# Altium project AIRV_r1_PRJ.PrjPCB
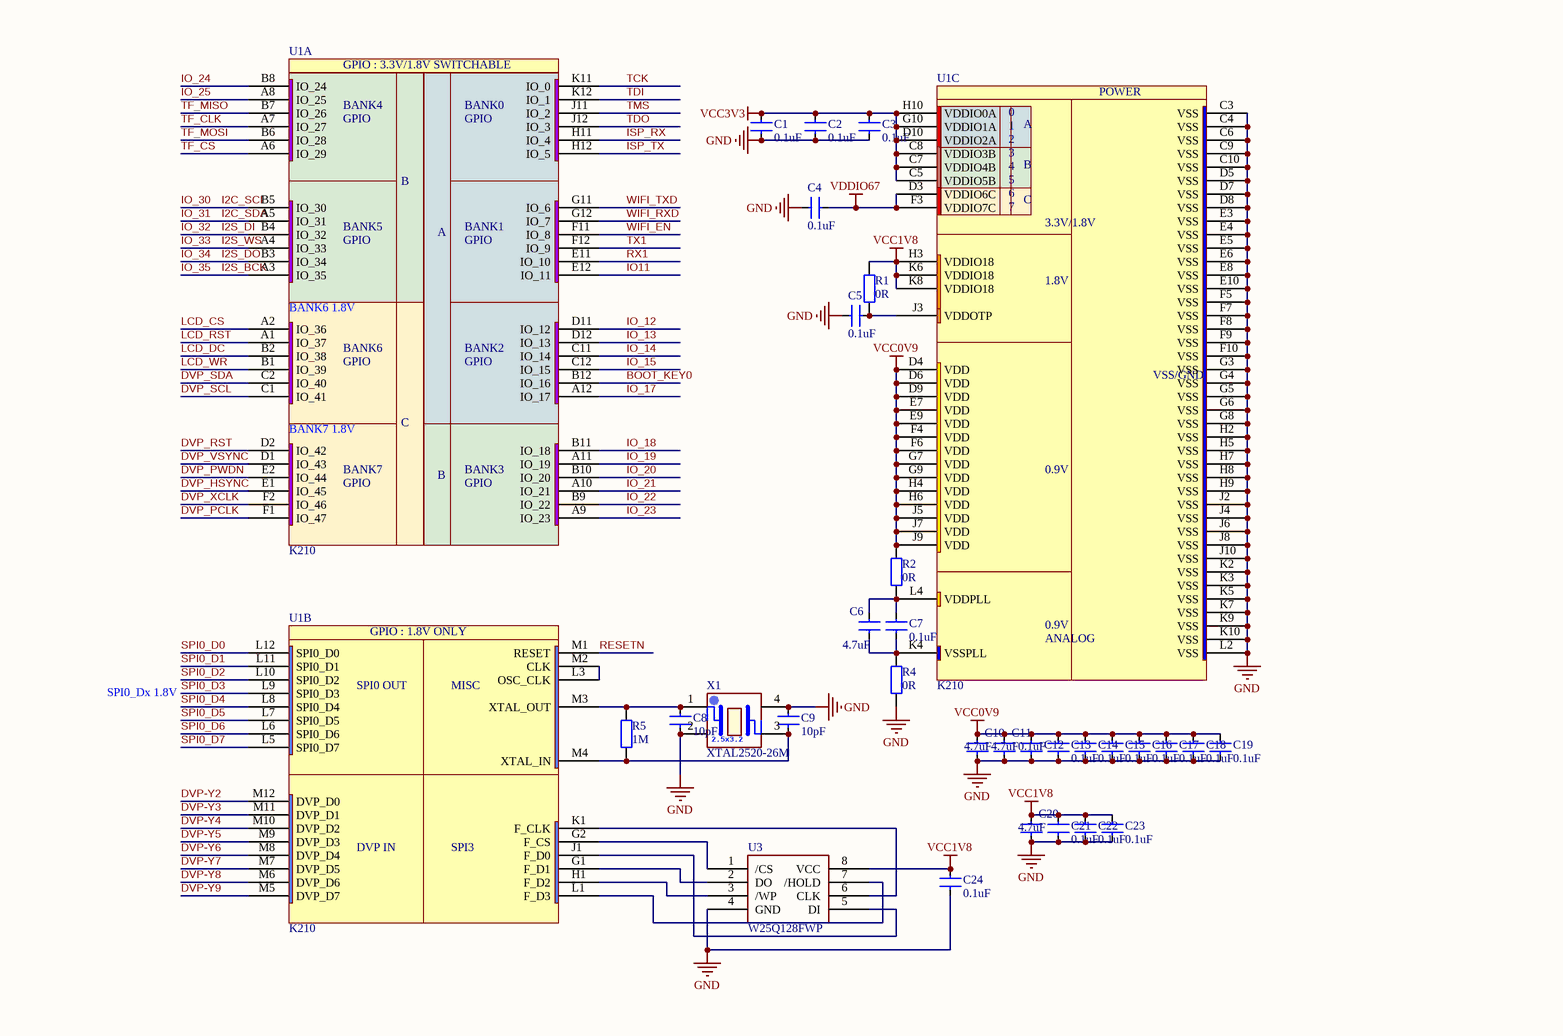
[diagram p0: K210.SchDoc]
2 sheets, 130 parts. Net scope: global (net labels, ports and power ports of the same name join across sheets).
Board file: AIRV_r1_nologo.PcbDoc
Sheets:
  K210.SchDoc
  Periph.SchDoc

## Sheet K210.SchDoc: RF
size A4; Date: 20150330; DrawnBy: mango; DocumentNumber: 1; SheetNumber: 1; SheetTotal: 7

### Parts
C1  0.1uF  [C0402]
C2  0.1uF  [C0402]
C3  0.1uF  [C0402]
C4  0.1uF  [C0402]
C5  0.1uF  [C0402]
C6  4.7uF  [C0402]
C7  0.1uF  [C0402]
C8  10pF  [C0402]
C9  10pF  [C0402]
C10  4.7uF  [C0402]
C11  4.7uF  [C0402]
C12  0.1uF  [C0402]
C13  0.1uF  [C0402]
C14  0.1uF  [C0402]
C15  0.1uF  [C0402]
C16  0.1uF  [C0402]
C17  0.1uF  [C0402]
C18  0.1uF  [C0402]
C19  0.1uF  [C0402]
C20  4.7uF  [C0402]
C21  0.1uF  [C0402]
C22  0.1uF  [C0402]
C23  0.1uF  [C0402]
C24  0.1uF  [C0402]
R1  0R  [R0402]
R2  0R  [R0402]
R4  0R  [R0402]
R5  1M  [R0402]
U1  K210  [BGA144C65P12X12_800X800X95]  (parts A,B,C of 3)
U3  W25Q128FWP  [WSON6X5]
X1  XTAL2520-26M  [XTAL2520]

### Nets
GND: C1.2 C2.2 C3.2 C4.2 C5.1 C8.1 C9.2 C10.1 C11.1 C12.1 C13.1 C14.1 C15.1 C16.1 C17.1 C18.1 C19.1 C20.1 C21.1 C22.1 C23.1 C24.1 R4.1 U1.C3(VSS) U1.C4(VSS) U1.C6(VSS) U1.C9(VSS) U1.C10(VSS) U1.D5(VSS) U1.D7(VSS) U1.D8(VSS) U1.E3(VSS) U1.E4(VSS) U1.E5(VSS) U1.E6(VSS) U1.E8(VSS) U1.E10(VSS) U1.F5(VSS) U1.F7(VSS) U1.F8(VSS) U1.F9(VSS) U1.F10(VSS) U1.G3(VSS) U1.G4(VSS) U1.G5(VSS) U1.G6(VSS) U1.G8(VSS) U1.H2(VSS) U1.H5(VSS) U1.H7(VSS) U1.H8(VSS) U1.H9(VSS) U1.J2(VSS) U1.J4(VSS) U1.J6(VSS) U1.J8(VSS) U1.J10(VSS) U1.K2(VSS) U1.K3(VSS) U1.K5(VSS) U1.K7(VSS) U1.K9(VSS) U1.K10(VSS) U1.L2(VSS) U3.4(GND) X1.2(NC1) X1.4(NC2)
VCC0V9: C10.2 C11.2 C12.2 C13.2 C14.2 C15.2 C16.2 C17.2 C18.2 C19.2 R2.2 U1.D4(VDD) U1.D6(VDD) U1.D9(VDD) U1.E7(VDD) U1.E9(VDD) U1.F4(VDD) U1.F6(VDD) U1.G7(VDD) U1.G9(VDD) U1.H4(VDD) U1.H6(VDD) U1.J5(VDD) U1.J7(VDD) U1.J9(VDD)
VCC1V8: C20.2 C21.2 C22.2 C23.2 C24.2 R1.1 U1.H3(VDDIO18) U1.K6(VDDIO18) U1.K8(VDDIO18) U3.8(VCC)
VCC3V3: C1.1 C2.1 C3.1 U1.C5(VDDIO5B) U1.C7(VDDIO4B) U1.C8(VDDIO3B) U1.D10(VDDIO2A) U1.G10(VDDIO1A) U1.H10(VDDIO0A)
VDDIO67: C4.1 U1.D3(VDDIO6C) U1.F3(VDDIO7C)
BOOT_KEY0: U1.B12(IO_16)
DVP-Y2: U1.M12(DVP_D0)
DVP-Y3: U1.M11(DVP_D1)
DVP-Y4: U1.M10(DVP_D2)
DVP-Y5: U1.M9(DVP_D3)
DVP-Y6: U1.M8(DVP_D4)
DVP-Y7: U1.M7(DVP_D5)
DVP-Y8: U1.M6(DVP_D6)
DVP-Y9: U1.M5(DVP_D7)
DVP_HSYNC: U1.E1(IO_45)
DVP_PCLK: U1.F1(IO_47)
DVP_PWDN: U1.E2(IO_44)
DVP_RST: U1.D2(IO_42)
DVP_SCL: U1.C1(IO_41)
DVP_SDA: U1.C2(IO_40)
DVP_VSYNC: U1.D1(IO_43)
DVP_XCLK: U1.F2(IO_46)
I2C_SCL: U1.B5(IO_30)  [also labelled IO_30]
I2C_SDA: U1.A5(IO_31)  [also labelled IO_31]
I2S_BCK: U1.A3(IO_35)  [also labelled IO_35]
I2S_DI: U1.B4(IO_32)  [also labelled IO_32]
I2S_DO: U1.B3(IO_34)  [also labelled IO_34]
I2S_WS: U1.A4(IO_33)  [also labelled IO_33]
IO11: U1.E12(IO_11)
IO_12: U1.D11(IO_12)
IO_13: U1.D12(IO_13)
IO_14: U1.C11(IO_14)
IO_15: U1.C12(IO_15)
IO_17: U1.A12(IO_17)
IO_18: U1.B11(IO_18)
IO_19: U1.A11(IO_19)
IO_20: U1.B10(IO_20)
IO_21: U1.A10(IO_21)
IO_22: U1.B9(IO_22)
IO_23: U1.A9(IO_23)
IO_24: U1.B8(IO_24)
IO_25: U1.A8(IO_25)
ISP_RX: U1.H11(IO_4)
ISP_TX: U1.H12(IO_5)
LCD_CS: U1.A2(IO_36)
LCD_DC: U1.B2(IO_38)
LCD_RST: U1.A1(IO_37)
LCD_WR: U1.B1(IO_39)
RESETN: U1.M1(RESET)
RX1: U1.E11(IO_10)
SPI0_D0: U1.L12(SPI0_D0)
SPI0_D1: U1.L11(SPI0_D1)
SPI0_D2: U1.L10(SPI0_D2)
SPI0_D3: U1.L9(SPI0_D3)
SPI0_D4: U1.L8(SPI0_D4)
SPI0_D5: U1.L7(SPI0_D5)
SPI0_D6: U1.L6(SPI0_D6)
SPI0_D7: U1.L5(SPI0_D7)
TCK: U1.K11(IO_0)
TDI: U1.K12(IO_1)
TDO: U1.J12(IO_3)
TF_CLK: U1.A7(IO_27)
TF_CS: U1.A6(IO_29)
TF_MISO: U1.B7(IO_26)
TF_MOSI: U1.B6(IO_28)
TMS: U1.J11(IO_2)
TX1: U1.F12(IO_9)
WIFI_EN: U1.F11(IO_8)
WIFI_RXD: U1.G12(IO_7)
WIFI_TXD: U1.G11(IO_6)
NetC5_2: C5.2 R1.2 U1.J3(VDDOTP)
NetC6_1: C6.1 C7.1 R4.2 U1.K4(VSSPLL)
NetC6_2: C6.2 C7.2 R2.1 U1.L4(VDDPLL)
NetC8_2: C8.2 R5.1 U1.M3(XTAL_OUT) X1.1(X1)
NetC9_1: C9.1 R5.2 U1.M4(XTAL_IN) X1.3(X2)
NetU1_G1: U1.G1(F_D1) U3.2(DO)
NetU1_G2: U1.G2(F_CS) U3.1(/CS)
NetU1_H1: U1.H1(F_D2) U3.3(/WP)
NetU1_J1: U1.J1(F_D0) U3.5(DI)
NetU1_K1: U1.K1(F_CLK) U3.6(CLK)
NetU1_L1: U1.L1(F_D3) U3.7(/HOLD)
NetU1_L3: U1.L3(OSC_CLK) U1.M2(CLK)

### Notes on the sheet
- (near U1) BANK6 1.8V
- (near U1) BANK7 1.8V
- SPI0_Dx 1.8V

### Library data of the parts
C1-C24 = CAP: 普通小电容
R1 R2 R4 R5 = RES: 普通电阻
U1 = K210: Canaan Kendryte K210 AI SoC; VENDOR: CANAAN INC.
U3 = SPIFLASH_SOP8W
X1 = XTAL3225

## Sheet Periph.SchDoc
size A3; DocumentNumber: 3; SheetNumber: 3; SheetTotal: 7
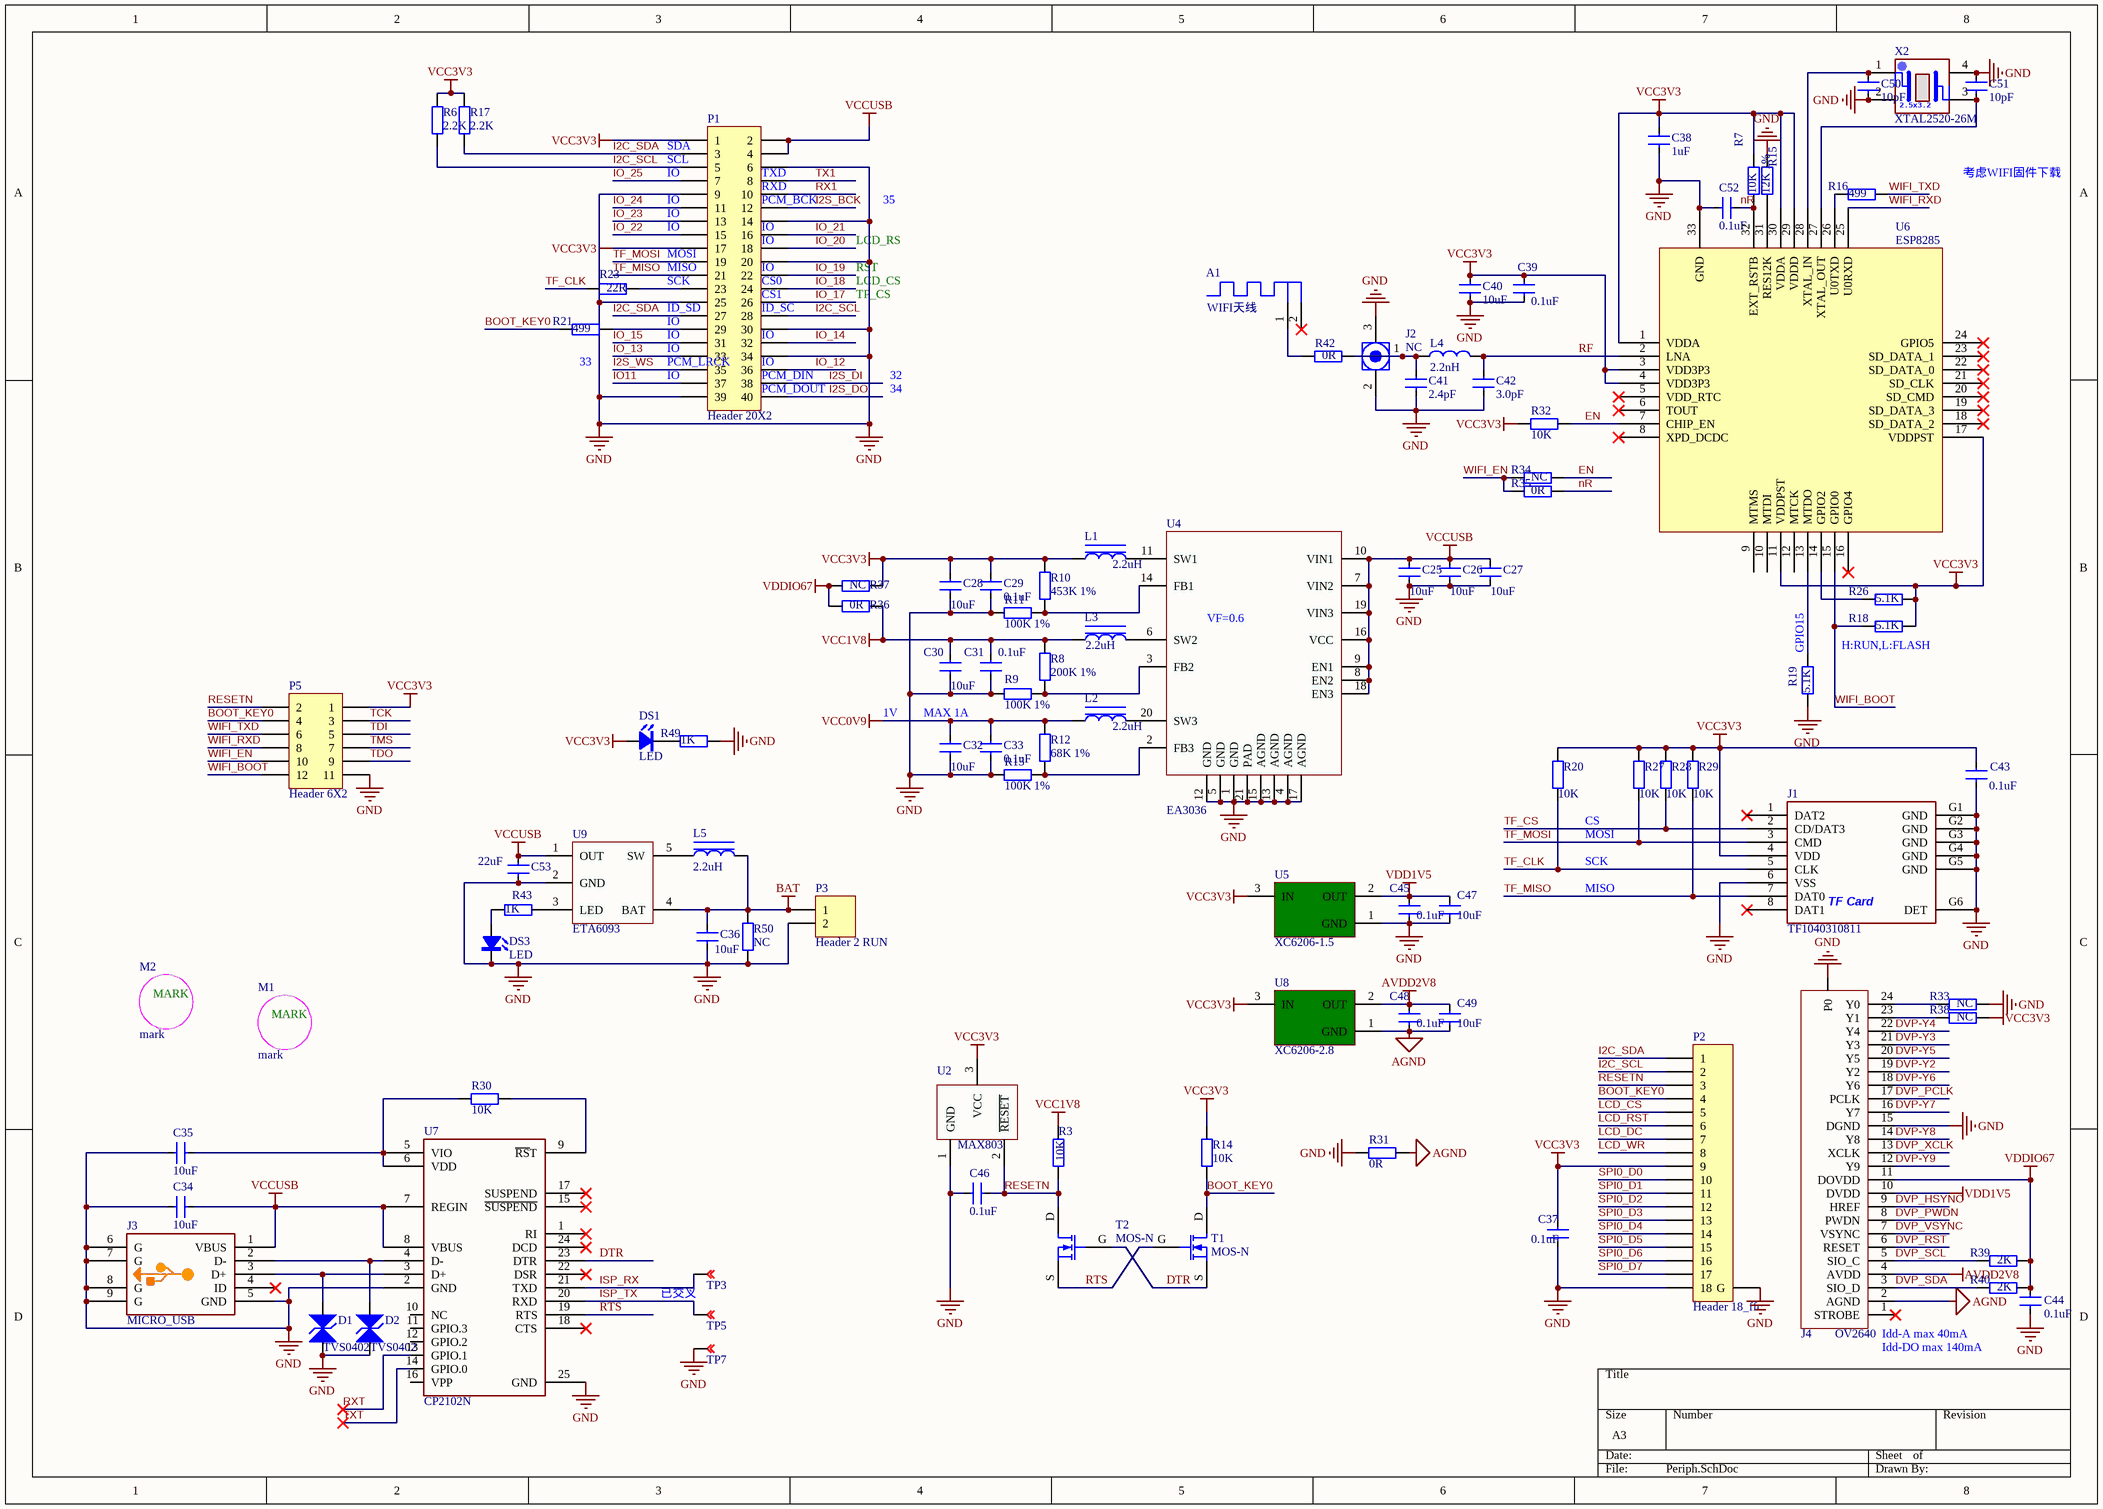
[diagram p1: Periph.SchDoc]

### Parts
A1  WIFI天线  [AN3216]
C25  10uF  [C0402]
C26  10uF  [C0402]
C27  10uF  [C0402]
C28  10uF  [C0402]
C29  0.1uF  [C0402]
C30  10uF  [C0402]
C31  0.1uF  [C0402]
C32  10uF  [C0402]
C33  0.1uF  [C0402]
C34  10uF  [C0402]
C35  10uF  [C0402]
C36  10uF  [C0402]
C37  0.1uF  [C0402]
C38  1uF  [C0402]
C39  0.1uF  [C0402]
C40  10uF  [C0402]
C41  2.4pF  [C0402]
C42  3.0pF  [C0402]
C43  0.1uF  [C0402]
C44  0.1uF  [C0402]
C45  0.1uF  [C0402]
C46  0.1uF  [C0402]
C47  10uF  [C0402]
C48  0.1uF  [C0402]
C49  10uF  [C0402]
C50  10pF  [C0402]
C51  10pF  [C0402]
C52  0.1uF  [C0402]
C53  22uF  [C0603]
D1  TVS0402  [0402TVS]
D2  TVS0402  [0402TVS]
DS1  LED  [LED0603]
DS3  LED  [LED0603]
J1  TF1040310811  [TFCARD-1040310811]
J2  NC  [I-PEX SOCKET]
J3  MICRO_USB  [MICROUSB]
J4  OV2640  [FFC/SM0.5-2H24-OV5640]
L1  2.2uH  [VLS2016]
L2  2.2uH  [VLS2016]
L3  2.2uH  [VLS2016]
L4  2.2nH  [L0402]
L5  2.2uH  [VLS2016]
M1  mark  [ZY_UR-3X2]
M2  mark  [MARKER-C]
P1  Header 20X2  [HDR2X20]
P2  Header 18_ffc  [FFC/SM0.5-1H18]
P3  Header 2 RUN  [HDR1X2]
P5  Header 6X2  [HDR1.27-6x2]
R3  10K  [R0402]
R6  2.2K  [R0402]
R7  10K  [R0402]
R8  200K 1%  [R0402]
R9  100K 1%  [R0402]
R10  453K 1%  [R0402]
R11  100K 1%  [R0402]
R12  68K 1%  [R0402]
R13  100K 1%  [R0402]
R14  10K  [R0402]
R15  12K 1%  [R0402]
R16  499  [R0402]
R17  2.2K  [R0402]
R18  5.1K  [R0402]
R19  5.1K  [R0402]
R20  10K  [R0402]
R21  499  [R0402]
R23  22R  [R0402]
R26  5.1K  [R0402]
R27  10K  [R0402]
R28  10K  [R0402]
R29  10K  [R0402]
R30  10K  [R0402]
R31  0R  [R0402]
R32  10K  [R0402]
R33  NC  [R0402]
R34  NC  [R0402]
R35  0R  [R0402]
R36  0R  [R0402]
R37  NC  [R0402]
R38  NC  [R0402]
R39  2K  [R0402]
R40  2K  [R0402]
R42  0R  [R0402]
R43  1K  [R0402]
R49  1K  [R0402]
R50  NC  [R0402]
T1  MOS-N  [SOT23]
T2  MOS-N  [SOT23]
TP3  TEST POINT  [TEST-POINT]  (value not drawn)
TP5  TEST POINT  [TEST-POINT]  (value not drawn)
TP7  TEST POINT  [TEST-POINT]  (value not drawn)
U2  MAX803  [SOT23]
U4  EA3036  [QFN40P300X300X80_HS-21N]
U5  XC6206-1.5  [SOT23]
U6  ESP8285  [QFN32]
U7  CP2102N  [QFN24]
U8  XC6206-2.8  [SOT23]
U9  ETA6093  [SOT23-5]
X2  XTAL2520-26M  [XTAL2520]

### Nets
AGND: C48.1 C49.2 J4.2(AGND) R31.2 U8.1(GND)
AVDD2V8: C48.2 C49.1 J4.4(AVDD) U8.2(OUT)
BAT: C36.1 L5.1 P3.1 R50.1 U9.4(BAT)
GND: C25.2 C26.2 C27.2 C28.2 C29.1 C30.2 C31.1 C32.2 C33.1 C34.1 C35.1 C36.2 C37.1 C38.1 C39.1 C40.1 C41.1 C42.1 C43.2 C44.1 C45.1 C46.1 C47.2 C50.1 C51.2 C52.2 C53.1 D1.1 D2.1 DS3.K J1.6(VSS) J1.G1(GND) J1.G2(GND) J1.G3(GND) J1.G4(GND) J1.G5(GND) J1.G6(DET) J2.2(GND) J2.3(GND) J3.5(GND) J3.6(G) J3.7(G) J3.8(G) J3.9(G) J4.15(DGND) J4.P0 P1.6 P1.9 P1.14 P1.20 P1.25 P1.30 P1.34 P1.39 P2.18 P2.G P3.2 P5.11 R9.2 R11.2 R13.2 R15.2 R19.1 R31.1 R33.2 R49.1 R50.2 TP7.1 U2.1(GND) U4.1(GND) U4.4(AGND) U4.5(GND) U4.12(GND) U4.13(AGND) U4.15(AGND) U4.17(AGND) U4.21(PAD) U5.1(GND) U6.33(GND) U7.2(GND) U7.25(GND) U9.2(GND) X2.2(NC1) X2.4(NC2)
VCC0V9: C32.1 C33.2 L2.2 R12.1
VCC1V8: C30.1 C31.2 L3.2 R3.2 R8.1 R36.2
VCC3V3: C28.1 C29.2 C37.2 C38.2 C39.2 C40.2 C43.1 DS1.A J1.4(VDD) L1.2 P1.1 P1.17 P2.9 P5.1 R6.2 R7.1 R10.1 R14.1 R17.2 R18.1 R20.1 R26.1 R27.1 R28.1 R29.1 R32.2 R37.2 R38.2 U2.3(VCC) U5.3(IN) U6.1(VDDA) U6.3(VDD3P3) U6.4(VDD3P3) U6.11(VDDPST) U6.17(VDDPST) U6.29(VDDD) U6.30(VDDA) U8.3(IN)
VCCUSB: C25.1 C26.1 C27.1 C34.2 C53.2 J3.1(VBUS) P1.2 P1.4 U4.7(VIN2) U4.8(EN2) U4.9(EN1) U4.10(VIN1) U4.16(VCC) U4.18(EN3) U4.19(VIN3) U7.7(REGIN) U7.8(VBUS) U9.1(OUT)
VDD1V5: C45.2 C47.1 J4.10(DVDD) U5.2(OUT)
VDDIO67: C44.2 J4.11(DOVDD) R36.1 R37.1 R39.2 R40.2
BOOT_KEY0: P2.4 P5.4 R14.2 R21.2 T1.D
DTR: T1.S T2.G U7.23(DTR)
DVP-Y2: J4.19(Y2)
DVP-Y3: J4.21(Y3)
DVP-Y4: J4.22(Y4)
DVP-Y5: J4.20(Y5)
DVP-Y6: J4.18(Y6)
DVP-Y7: J4.16(Y7)
DVP-Y8: J4.14(Y8)
DVP-Y9: J4.12(Y9)
DVP_HSYNC: J4.9(HREF)
DVP_PCLK: J4.17(PCLK)
DVP_PWDN: J4.8(PWDN)
DVP_RST: J4.6(RESET)
DVP_SCL: J4.5(SIO_C) R39.1
DVP_SDA: J4.3(SIO_D) R40.1
DVP_VSYNC: J4.7(VSYNC)
DVP_XCLK: J4.13(XCLK)
EN: R32.1 R34.1 U6.7(CHIP_EN)
I2C_SCL: P1.5 P1.28 P2.2 R6.1
I2C_SDA: P1.3 P1.27 P2.1 R17.1
I2S_BCK: P1.12
I2S_DI: P1.38
I2S_DO: P1.40
I2S_WS: P1.35
IO11: P1.37
IO_12: P1.36
IO_13: P1.33
IO_14: P1.32
IO_15: P1.31
IO_17: P1.26
IO_18: P1.24
IO_19: P1.22
IO_20: P1.18
IO_21: P1.16
IO_22: P1.15
IO_23: P1.13
IO_24: P1.11
IO_25: P1.7
ISP_RX: TP3.1 U7.21(TXD)
ISP_TX: TP5.1 U7.20(RXD)
LCD_CS: P2.5
LCD_DC: P2.7
LCD_RST: P2.6
LCD_WR: P2.8
nR: C52.1 R7.2 R35.1 U6.32(EXT_RSTB)
RESETN: C46.2 P2.3 P5.2 R3.1 T2.D U2.2(~{RESET})
RF: C42.2 L4.1 U6.2(LNA)
RTS: T1.G T2.S U7.19(RTS)
RX1: P1.10
RXT: U7.13(GPIO.1)
SPI0_D0: P2.10
SPI0_D1: P2.11
SPI0_D2: P2.12
SPI0_D3: P2.13
SPI0_D4: P2.14
SPI0_D5: P2.15
SPI0_D6: P2.16
SPI0_D7: P2.17
TCK: P5.3
TDI: P5.5
TDO: P5.9
TF_CLK: J1.5(CLK) R20.2 R23.1
TF_CS: J1.2(CD/DAT3) R28.2
TF_MISO: J1.7(DAT0) P1.21 R29.2
TF_MOSI: J1.3(CMD) P1.19 R27.2
TMS: P5.7
TX1: P1.8
TXT: U7.14(GPIO.0)
WIFI_BOOT: P5.12 R18.2 U6.15(GPIO0)
WIFI_EN: P5.10 R34.2 R35.2
WIFI_RXD: P5.8 U6.25(U0RXD)
WIFI_TXD: P5.6 R16.1
NetA1_1: A1.1 R42.1
NetC35_2: C35.2 R30.2 U7.5(VIO) U7.6(VDD)
NetC41_2: C41.2 J2.1(Signal) L4.2 R42.2
NetC50_2: C50.2 U6.28(XTAL_IN) X2.1(X1)
NetC51_1: C51.1 U6.27(XTAL_OUT) X2.3(X2)
NetD1_2: D1.2 J3.3(D+) U7.3(D+)
NetD2_2: D2.2 J3.2(D-) U7.4(D-)
NetDS1_K: DS1.K R49.2
NetDS3_A: DS3.A R43.2
NetJ4_23: J4.23(Y1) R38.1
NetJ4_24: J4.24(Y0) R33.1
NetL1_1: L1.1 U4.11(SW1)
NetL2_1: L2.1 U4.20(SW3)
NetL3_1: L3.1 U4.6(SW2)
NetL5_2: L5.2 U9.5(SW)
NetP1_23: P1.23 R23.2
NetP1_29: P1.29 R21.1
NetR8_2: R8.2 R9.1 U4.3(FB2)
NetR10_2: R10.2 R11.1 U4.14(FB1)
NetR12_2: R12.2 R13.1 U4.2(FB3)
NetR15_1: R15.1 U6.31(RES12K)
NetR16_2: R16.2 U6.26(U0TXD)
NetR19_2: R19.2 U6.13(MTDO)
NetR26_2: R26.2 U6.14(GPIO2)
NetR30_1: R30.1 U7.9(~{RS}T)
NetR43_1: R43.1 U9.3(LED)

Not connected (* = marked no-connect by the designer): A1 2(G)*; J1 1(DAT2)* 8(DAT1)*; J3 4(ID)*; J4 1(STROBE)*; U6 5(VDD_RTC)* 6(TOUT)* 8(XPD_DCDC)* 9(MTMS) 10(MTDI) 12(MTCK) 16(GPIO4)* 18(SD_DATA_2)* 19(SD_DATA_3)* 20(SD_CMD)* 21(SD_CLK)* 22(SD_DATA_0)* 23(SD_DATA_1)* 24(GPIO5)*; U7 1(RI)* 10(NC) 11(GPIO.3) 12(GPIO.2) 15(~{SUSPEND})* 16(VPP) 17(SUSPEND)* 18(CTS)* 22(DSR)* 24(DCD)*

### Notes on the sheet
- (near P1) SDA
- (near P1) SCL
- (near P1) IO
- (near P1) TXD
- 考虑WIFI固件下载
- (near P1) RXD
- (near P1) PCM_BCK
- LCD_RS
- 35
- (near P1) MOSI
- (near P1) MISO
- (near P1) SCK
- (near P1) ID_SD
- (near P1) CS0
- (near P1) CS1
- (near P1) ID_SC
- RST
- LCD_CS
- TP_CS
- (near R21) 33
- (near P1) PCM_LRCK
- (near P1) PCM_DIN
- 32
- (near P1) PCM_DOUT
- 34
- (near U4) VF=0.6
- (near R19) GPIO15
- (near R18) H:RUN,L:FLASH
- 1V
- MAX 1A
- MOSI
- CS
- MISO
- SCK
- 已交叉
- (near J4) Idd-A max 40mA
- (near J4) Idd-DO max 140mA

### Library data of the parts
A1 = ANT2.4G
C25-C53 = CAP: 普通小电容
D1 D2 = D-TVS: TVS放电管SMBJ5.0CA
J1 = TF5033981892
J2 = MCX_IPEX
J4 = OV5640: Header, 24-Pin
L1-L3 L5 = L: 普通电感
L4 = L0402
P1 = Header 20X2: Header, 20-Pin, Dual row
P2 = Header 18_ffc: Header, 18-Pin
P3 = Header 2: Header, 2-Pin
P5 = Header 6X2: Header, 6-Pin, Dual row
R3 R6-R21 R23 R26-R40 R42 R43 R49 R50 = RES: 普通电阻
T1 T2 = MOS-N: pin to pad: D>3 G>1 S>2
TP3 TP5 TP7 = TP: Description
U2 = MAX809
U5 U8 = XC6206
U6 = ESP8266EX: ESP8285 IOT SOC
U7 = CP2104
X2 = XTAL3225

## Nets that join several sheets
GND: K210 (67 pins), Periph (84 pins)
VCC0V9: K210 (25 pins), Periph (C32.1 C33.2 L2.2 R12.1)
VCC1V8: K210 (10 pins), Periph (6 pins)
VCC3V3: K210 (9 pins), Periph (38 pins)
VDDIO67: K210 (C4.1 U1.D3 U1.F3), Periph (6 pins)
BOOT_KEY0: K210 (U1.B12), Periph (5 pins)
DVP-Y2: K210 (U1.M12), Periph (J4.19)
DVP-Y3: K210 (U1.M11), Periph (J4.21)
DVP-Y4: K210 (U1.M10), Periph (J4.22)
DVP-Y5: K210 (U1.M9), Periph (J4.20)
DVP-Y6: K210 (U1.M8), Periph (J4.18)
DVP-Y7: K210 (U1.M7), Periph (J4.16)
DVP-Y8: K210 (U1.M6), Periph (J4.14)
DVP-Y9: K210 (U1.M5), Periph (J4.12)
DVP_HSYNC: K210 (U1.E1), Periph (J4.9)
DVP_PCLK: K210 (U1.F1), Periph (J4.17)
DVP_PWDN: K210 (U1.E2), Periph (J4.8)
DVP_RST: K210 (U1.D2), Periph (J4.6)
DVP_SCL: K210 (U1.C1), Periph (J4.5 R39.1)
DVP_SDA: K210 (U1.C2), Periph (J4.3 R40.1)
DVP_VSYNC: K210 (U1.D1), Periph (J4.7)
DVP_XCLK: K210 (U1.F2), Periph (J4.13)
I2C_SCL: K210 (U1.B5), Periph (P1.5 P1.28 P2.2 R6.1)
I2C_SDA: K210 (U1.A5), Periph (P1.3 P1.27 P2.1 R17.1)
I2S_BCK: K210 (U1.A3), Periph (P1.12)
I2S_DI: K210 (U1.B4), Periph (P1.38)
I2S_DO: K210 (U1.B3), Periph (P1.40)
I2S_WS: K210 (U1.A4), Periph (P1.35)
IO11: K210 (U1.E12), Periph (P1.37)
IO_12: K210 (U1.D11), Periph (P1.36)
IO_13: K210 (U1.D12), Periph (P1.33)
IO_14: K210 (U1.C11), Periph (P1.32)
IO_15: K210 (U1.C12), Periph (P1.31)
IO_17: K210 (U1.A12), Periph (P1.26)
IO_18: K210 (U1.B11), Periph (P1.24)
IO_19: K210 (U1.A11), Periph (P1.22)
IO_20: K210 (U1.B10), Periph (P1.18)
IO_21: K210 (U1.A10), Periph (P1.16)
IO_22: K210 (U1.B9), Periph (P1.15)
IO_23: K210 (U1.A9), Periph (P1.13)
IO_24: K210 (U1.B8), Periph (P1.11)
IO_25: K210 (U1.A8), Periph (P1.7)
ISP_RX: K210 (U1.H11), Periph (TP3.1 U7.21)
ISP_TX: K210 (U1.H12), Periph (TP5.1 U7.20)
LCD_CS: K210 (U1.A2), Periph (P2.5)
LCD_DC: K210 (U1.B2), Periph (P2.7)
LCD_RST: K210 (U1.A1), Periph (P2.6)
LCD_WR: K210 (U1.B1), Periph (P2.8)
RESETN: K210 (U1.M1), Periph (6 pins)
RX1: K210 (U1.E11), Periph (P1.10)
SPI0_D0: K210 (U1.L12), Periph (P2.10)
SPI0_D1: K210 (U1.L11), Periph (P2.11)
SPI0_D2: K210 (U1.L10), Periph (P2.12)
SPI0_D3: K210 (U1.L9), Periph (P2.13)
SPI0_D4: K210 (U1.L8), Periph (P2.14)
SPI0_D5: K210 (U1.L7), Periph (P2.15)
SPI0_D6: K210 (U1.L6), Periph (P2.16)
SPI0_D7: K210 (U1.L5), Periph (P2.17)
TCK: K210 (U1.K11), Periph (P5.3)
TDI: K210 (U1.K12), Periph (P5.5)
TDO: K210 (U1.J12), Periph (P5.9)
TF_CLK: K210 (U1.A7), Periph (J1.5 R20.2 R23.1)
TF_CS: K210 (U1.A6), Periph (J1.2 R28.2)
TF_MISO: K210 (U1.B7), Periph (J1.7 P1.21 R29.2)
TF_MOSI: K210 (U1.B6), Periph (J1.3 P1.19 R27.2)
TMS: K210 (U1.J11), Periph (P5.7)
TX1: K210 (U1.F12), Periph (P1.8)
WIFI_EN: K210 (U1.F11), Periph (P5.10 R34.2 R35.2)
WIFI_RXD: K210 (U1.G12), Periph (P5.8 U6.25)
WIFI_TXD: K210 (U1.G11), Periph (P5.6 R16.1)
